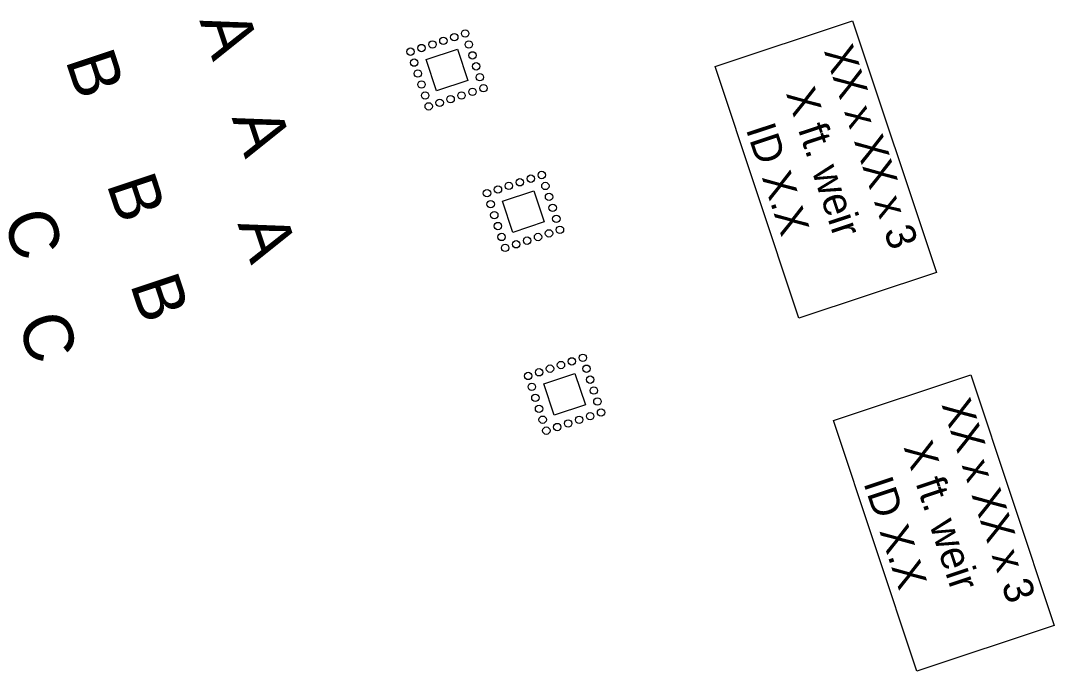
# Model space of a CAD drawing. Extents: x 400935 to 481562, y 415700 to 505362.
# Drawn here: x 402545.2 to 402858.9, y 417970 to 418167.5 of the extents above; entities that cross this region are included whole.
import ezdxf

# ---------------------------------------------------------------- set-up
doc = ezdxf.new("R2010")
doc.units = 0
for name, color, linetype in [('Label A Both CELL', 7, 'Continuous'), ('Label A CG CELL', 7, 'Continuous'), ('Label A Final CELL', 7, 'Continuous'), ('Label B Both CELL', 7, 'Continuous'), ('Label B CG CELL', 7, 'Continuous'), ('Label B Final CELL', 7, 'Continuous'), ('Label C Both CELL', 7, 'Continuous'), ('Label C Final CELL', 7, 'Continuous'), ('Rock Inlet Sediment Trap Type C Both CELL', 7, 'Continuous'), ('Rock Inlet Sediment Trap Type C CG CELL', 7, 'Continuous'), ('Rock Inlet Sediment Trap Type C Final CELL', 7, 'Continuous'), ('Sediment Dam B Note Both CELL', 7, 'Continuous'), ('Sediment Dam B Note Final CELL', 7, 'Continuous')]:
    doc.layers.add(name, color=color, linetype=linetype)

msp = doc.modelspace()

# ---------------------------------------------------------------- linework, layer by layer
at = {"layer": 'Rock Inlet Sediment Trap Type C Both CELL'}
msp.add_lwpolyline([(402700.96, 418115.87), (402704.11, 418106.38), (402694.62, 418103.22), (402691.48, 418112.72)], close=True, dxfattribs=at)
msp.add_lwpolyline([(402700.96, 418115.87), (402704.11, 418106.38), (402694.62, 418103.22), (402691.48, 418112.72)], close=True, dxfattribs=at)
msp.add_lwpolyline([(402700.96, 418115.87), (402704.11, 418106.38), (402694.62, 418103.22), (402691.48, 418112.72)], close=True, dxfattribs=at)
msp.add_lwpolyline([(402700.96, 418115.87), (402704.11, 418106.38), (402694.62, 418103.22), (402691.48, 418112.72)], close=True, dxfattribs=at)
msp.add_lwpolyline([(402700.96, 418115.87), (402704.11, 418106.38), (402694.62, 418103.22), (402691.48, 418112.72)], close=True, dxfattribs=at)
msp.add_lwpolyline([(402700.96, 418115.87), (402704.11, 418106.38), (402694.62, 418103.22), (402691.48, 418112.72)], close=True, dxfattribs=at)
for centre in [(402703.35, 418120.62), (402703.35, 418120.62), (402703.35, 418120.62), (402703.35, 418120.62), (402703.35, 418120.62), (402703.35, 418120.62), (402693.39, 418117.31), (402693.39, 418117.31), (402693.39, 418117.31), (402693.39, 418117.31), (402693.39, 418117.31), (402693.39, 418117.31), (402696.71, 418118.41), (402696.71, 418118.41), (402696.71, 418118.41), (402696.71, 418118.41), (402696.71, 418118.41), (402696.71, 418118.41), (402700.03, 418119.52), (402700.03, 418119.52), (402700.03, 418119.52), (402700.03, 418119.52), (402700.03, 418119.52), (402700.03, 418119.52), (402704.45, 418117.3), (402704.45, 418117.3), (402704.45, 418117.3), (402704.45, 418117.3), (402704.45, 418117.3), (402704.45, 418117.3), (402686.74, 418115.1), (402686.74, 418115.1), (402686.74, 418115.1), (402686.74, 418115.1), (402686.74, 418115.1), (402686.74, 418115.1), (402690.06, 418116.21), (402690.06, 418116.21), (402690.06, 418116.21), (402690.06, 418116.21), (402690.06, 418116.21), (402690.06, 418116.21), (402705.56, 418113.98), (402705.56, 418113.98), (402705.56, 418113.98), (402705.56, 418113.98), (402705.56, 418113.98), (402705.56, 418113.98), (402687.85, 418111.78), (402687.85, 418111.78), (402687.85, 418111.78), (402687.85, 418111.78), (402687.85, 418111.78), (402687.85, 418111.78), (402688.95, 418108.46), (402688.95, 418108.46), (402688.95, 418108.46), (402688.95, 418108.46), (402688.95, 418108.46), (402688.95, 418108.46), (402706.66, 418110.66), (402706.66, 418110.66), (402706.66, 418110.66), (402706.66, 418110.66), (402706.66, 418110.66), (402706.66, 418110.66), (402690.05, 418105.14), (402690.05, 418105.14), (402690.05, 418105.14), (402690.05, 418105.14), (402690.05, 418105.14), (402690.05, 418105.14), (402707.77, 418107.34), (402707.77, 418107.34), (402707.77, 418107.34), (402707.77, 418107.34), (402707.77, 418107.34), (402707.77, 418107.34), (402691.16, 418101.82), (402691.16, 418101.82), (402691.16, 418101.82), (402691.16, 418101.82), (402691.16, 418101.82), (402691.16, 418101.82), (402702.23, 418101.81), (402702.23, 418101.81), (402702.23, 418101.81), (402702.23, 418101.81), (402702.23, 418101.81), (402702.23, 418101.81), (402705.55, 418102.91), (402705.55, 418102.91), (402705.55, 418102.91), (402705.55, 418102.91), (402705.55, 418102.91), (402705.55, 418102.91), (402708.87, 418104.01), (402708.87, 418104.01), (402708.87, 418104.01), (402708.87, 418104.01), (402708.87, 418104.01), (402708.87, 418104.01), (402692.26, 418098.5), (402692.26, 418098.5), (402692.26, 418098.5), (402692.26, 418098.5), (402692.26, 418098.5), (402692.26, 418098.5), (402695.58, 418099.6), (402695.58, 418099.6), (402695.58, 418099.6), (402695.58, 418099.6), (402695.58, 418099.6), (402695.58, 418099.6), (402698.9, 418100.7), (402698.9, 418100.7), (402698.9, 418100.7), (402698.9, 418100.7), (402698.9, 418100.7), (402698.9, 418100.7)]:
    msp.add_circle(centre, 1.12, dxfattribs=at)
at = {"layer": 'Rock Inlet Sediment Trap Type C CG CELL'}
msp.add_lwpolyline([(402677.74, 418158.82), (402680.9, 418149.33), (402671.41, 418146.17), (402668.26, 418155.67)], close=True, dxfattribs=at)
msp.add_lwpolyline([(402677.74, 418158.82), (402680.9, 418149.33), (402671.41, 418146.17), (402668.26, 418155.67)], close=True, dxfattribs=at)
msp.add_lwpolyline([(402677.74, 418158.82), (402680.9, 418149.33), (402671.41, 418146.17), (402668.26, 418155.67)], close=True, dxfattribs=at)
msp.add_lwpolyline([(402677.74, 418158.82), (402680.9, 418149.33), (402671.41, 418146.17), (402668.26, 418155.67)], close=True, dxfattribs=at)
msp.add_lwpolyline([(402677.74, 418158.82), (402680.9, 418149.33), (402671.41, 418146.17), (402668.26, 418155.67)], close=True, dxfattribs=at)
msp.add_lwpolyline([(402677.74, 418158.82), (402680.9, 418149.33), (402671.41, 418146.17), (402668.26, 418155.67)], close=True, dxfattribs=at)
for centre in [(402673.49, 418161.36), (402673.49, 418161.36), (402673.49, 418161.36), (402673.49, 418161.36), (402673.49, 418161.36), (402673.49, 418161.36), (402676.81, 418162.47), (402676.81, 418162.47), (402676.81, 418162.47), (402676.81, 418162.47), (402676.81, 418162.47), (402676.81, 418162.47), (402680.13, 418163.57), (402680.13, 418163.57), (402680.13, 418163.57), (402680.13, 418163.57), (402680.13, 418163.57), (402680.13, 418163.57), (402663.53, 418158.05), (402663.53, 418158.05), (402663.53, 418158.05), (402663.53, 418158.05), (402663.53, 418158.05), (402663.53, 418158.05), (402666.85, 418159.16), (402666.85, 418159.16), (402666.85, 418159.16), (402666.85, 418159.16), (402666.85, 418159.16), (402666.85, 418159.16), (402670.17, 418160.26), (402670.17, 418160.26), (402670.17, 418160.26), (402670.17, 418160.26), (402670.17, 418160.26), (402670.17, 418160.26), (402681.24, 418160.25), (402681.24, 418160.25), (402681.24, 418160.25), (402681.24, 418160.25), (402681.24, 418160.25), (402681.24, 418160.25), (402664.63, 418154.73), (402664.63, 418154.73), (402664.63, 418154.73), (402664.63, 418154.73), (402664.63, 418154.73), (402664.63, 418154.73), (402682.34, 418156.93), (402682.34, 418156.93), (402682.34, 418156.93), (402682.34, 418156.93), (402682.34, 418156.93), (402682.34, 418156.93), (402683.44, 418153.61), (402683.44, 418153.61), (402683.44, 418153.61), (402683.44, 418153.61), (402683.44, 418153.61), (402683.44, 418153.61), (402665.73, 418151.41), (402665.73, 418151.41), (402665.73, 418151.41), (402665.73, 418151.41), (402665.73, 418151.41), (402665.73, 418151.41), (402684.55, 418150.29), (402684.55, 418150.29), (402684.55, 418150.29), (402684.55, 418150.29), (402684.55, 418150.29), (402684.55, 418150.29), (402666.84, 418148.09), (402666.84, 418148.09), (402666.84, 418148.09), (402666.84, 418148.09), (402666.84, 418148.09), (402666.84, 418148.09), (402682.33, 418145.86), (402682.33, 418145.86), (402682.33, 418145.86), (402682.33, 418145.86), (402682.33, 418145.86), (402682.33, 418145.86), (402685.65, 418146.96), (402685.65, 418146.96), (402685.65, 418146.96), (402685.65, 418146.96), (402685.65, 418146.96), (402685.65, 418146.96), (402667.94, 418144.77), (402667.94, 418144.77), (402667.94, 418144.77), (402667.94, 418144.77), (402667.94, 418144.77), (402667.94, 418144.77), (402672.37, 418142.55), (402672.37, 418142.55), (402672.37, 418142.55), (402672.37, 418142.55), (402672.37, 418142.55), (402672.37, 418142.55), (402675.69, 418143.65), (402675.69, 418143.65), (402675.69, 418143.65), (402675.69, 418143.65), (402675.69, 418143.65), (402675.69, 418143.65), (402679.01, 418144.76), (402679.01, 418144.76), (402679.01, 418144.76), (402679.01, 418144.76), (402679.01, 418144.76), (402679.01, 418144.76), (402669.04, 418141.45), (402669.04, 418141.45), (402669.04, 418141.45), (402669.04, 418141.45), (402669.04, 418141.45), (402669.04, 418141.45)]:
    msp.add_circle(centre, 1.12, dxfattribs=at)
at = {"layer": 'Rock Inlet Sediment Trap Type C Final CELL'}
msp.add_lwpolyline([(402713.43, 418060.41), (402716.59, 418050.92), (402707.1, 418047.76), (402703.96, 418057.26)], close=True, dxfattribs=at)
msp.add_lwpolyline([(402713.43, 418060.41), (402716.59, 418050.92), (402707.1, 418047.76), (402703.96, 418057.26)], close=True, dxfattribs=at)
msp.add_lwpolyline([(402713.43, 418060.41), (402716.59, 418050.92), (402707.1, 418047.76), (402703.96, 418057.26)], close=True, dxfattribs=at)
msp.add_lwpolyline([(402713.43, 418060.41), (402716.59, 418050.92), (402707.1, 418047.76), (402703.96, 418057.26)], close=True, dxfattribs=at)
msp.add_lwpolyline([(402713.43, 418060.41), (402716.59, 418050.92), (402707.1, 418047.76), (402703.96, 418057.26)], close=True, dxfattribs=at)
msp.add_lwpolyline([(402713.43, 418060.41), (402716.59, 418050.92), (402707.1, 418047.76), (402703.96, 418057.26)], close=True, dxfattribs=at)
for centre in [(402712.5, 418064.06), (402712.5, 418064.06), (402712.5, 418064.06), (402712.5, 418064.06), (402712.5, 418064.06), (402712.5, 418064.06), (402715.82, 418065.16), (402715.82, 418065.16), (402715.82, 418065.16), (402715.82, 418065.16), (402715.82, 418065.16), (402715.82, 418065.16), (402702.54, 418060.75), (402702.54, 418060.75), (402702.54, 418060.75), (402702.54, 418060.75), (402702.54, 418060.75), (402702.54, 418060.75), (402705.86, 418061.85), (402705.86, 418061.85), (402705.86, 418061.85), (402705.86, 418061.85), (402705.86, 418061.85), (402705.86, 418061.85), (402709.18, 418062.95), (402709.18, 418062.95), (402709.18, 418062.95), (402709.18, 418062.95), (402709.18, 418062.95), (402709.18, 418062.95), (402716.93, 418061.84), (402716.93, 418061.84), (402716.93, 418061.84), (402716.93, 418061.84), (402716.93, 418061.84), (402716.93, 418061.84), (402699.22, 418059.64), (402699.22, 418059.64), (402699.22, 418059.64), (402699.22, 418059.64), (402699.22, 418059.64), (402699.22, 418059.64), (402718.03, 418058.52), (402718.03, 418058.52), (402718.03, 418058.52), (402718.03, 418058.52), (402718.03, 418058.52), (402718.03, 418058.52), (402700.32, 418056.32), (402700.32, 418056.32), (402700.32, 418056.32), (402700.32, 418056.32), (402700.32, 418056.32), (402700.32, 418056.32), (402719.14, 418055.2), (402719.14, 418055.2), (402719.14, 418055.2), (402719.14, 418055.2), (402719.14, 418055.2), (402719.14, 418055.2), (402701.42, 418053), (402701.42, 418053), (402701.42, 418053), (402701.42, 418053), (402701.42, 418053), (402701.42, 418053), (402720.24, 418051.88), (402720.24, 418051.88), (402720.24, 418051.88), (402720.24, 418051.88), (402720.24, 418051.88), (402720.24, 418051.88), (402702.53, 418049.68), (402702.53, 418049.68), (402702.53, 418049.68), (402702.53, 418049.68), (402702.53, 418049.68), (402702.53, 418049.68), (402721.34, 418048.55), (402721.34, 418048.55), (402721.34, 418048.55), (402721.34, 418048.55), (402721.34, 418048.55), (402721.34, 418048.55), (402703.63, 418046.36), (402703.63, 418046.36), (402703.63, 418046.36), (402703.63, 418046.36), (402703.63, 418046.36), (402703.63, 418046.36), (402711.38, 418045.24), (402711.38, 418045.24), (402711.38, 418045.24), (402711.38, 418045.24), (402711.38, 418045.24), (402711.38, 418045.24), (402714.7, 418046.35), (402714.7, 418046.35), (402714.7, 418046.35), (402714.7, 418046.35), (402714.7, 418046.35), (402714.7, 418046.35), (402718.02, 418047.45), (402718.02, 418047.45), (402718.02, 418047.45), (402718.02, 418047.45), (402718.02, 418047.45), (402718.02, 418047.45), (402704.74, 418043.04), (402704.74, 418043.04), (402704.74, 418043.04), (402704.74, 418043.04), (402704.74, 418043.04), (402704.74, 418043.04), (402708.06, 418044.14), (402708.06, 418044.14), (402708.06, 418044.14), (402708.06, 418044.14), (402708.06, 418044.14), (402708.06, 418044.14)]:
    msp.add_circle(centre, 1.12, dxfattribs=at)
at = {"layer": 'Sediment Dam B Note Both CELL'}
msp.add_lwpolyline([(402797.71, 418167.46), (402823.11, 418091.04), (402781.39, 418077.17), (402755.98, 418153.59)], close=True, dxfattribs=at)
msp.add_lwpolyline([(402797.71, 418167.46), (402823.11, 418091.04), (402781.39, 418077.17), (402755.98, 418153.59)], close=True, dxfattribs=at)
msp.add_lwpolyline([(402797.71, 418167.46), (402823.11, 418091.04), (402781.39, 418077.17), (402755.98, 418153.59)], close=True, dxfattribs=at)
msp.add_lwpolyline([(402797.71, 418167.46), (402823.11, 418091.04), (402781.39, 418077.17), (402755.98, 418153.59)], close=True, dxfattribs=at)
msp.add_lwpolyline([(402797.71, 418167.46), (402823.11, 418091.04), (402781.39, 418077.17), (402755.98, 418153.59)], close=True, dxfattribs=at)
msp.add_lwpolyline([(402797.71, 418167.46), (402823.11, 418091.04), (402781.39, 418077.17), (402755.98, 418153.59)], close=True, dxfattribs=at)
at = {"layer": 'Sediment Dam B Note Final CELL'}
msp.add_lwpolyline([(402833.61, 418059.98), (402858.91, 417983.87), (402817.18, 417970), (402791.89, 418046.1)], close=True, dxfattribs=at)
msp.add_lwpolyline([(402833.61, 418059.98), (402858.91, 417983.87), (402817.18, 417970), (402791.89, 418046.1)], close=True, dxfattribs=at)
msp.add_lwpolyline([(402833.61, 418059.98), (402858.91, 417983.87), (402817.18, 417970), (402791.89, 418046.1)], close=True, dxfattribs=at)
msp.add_lwpolyline([(402833.61, 418059.98), (402858.91, 417983.87), (402817.18, 417970), (402791.89, 418046.1)], close=True, dxfattribs=at)
msp.add_lwpolyline([(402833.61, 418059.98), (402858.91, 417983.87), (402817.18, 417970), (402791.89, 418046.1)], close=True, dxfattribs=at)
msp.add_lwpolyline([(402833.61, 418059.98), (402858.91, 417983.87), (402817.18, 417970), (402791.89, 418046.1)], close=True, dxfattribs=at)

# ---------------------------------------------------------------- texts
at = {"layer": 'Label A Both CELL'}
msp.add_text('A', height=15, rotation=288.3867, dxfattribs=at).set_placement((402609.21, 418137.97))
msp.add_text('A', height=15, rotation=288.3867, dxfattribs=at).set_placement((402609.21, 418137.97))
msp.add_text('A', height=15, rotation=288.3867, dxfattribs=at).set_placement((402609.21, 418137.97))
msp.add_text('A', height=15, rotation=288.3867, dxfattribs=at).set_placement((402609.21, 418137.97))
msp.add_text('A', height=15, rotation=288.3867, dxfattribs=at).set_placement((402609.21, 418137.97))
msp.add_text('A', height=15, rotation=288.3867, dxfattribs=at).set_placement((402609.21, 418137.97))
at = {"layer": 'Label A CG CELL'}
msp.add_text('A', height=15, rotation=288.3867, dxfattribs=at).set_placement((402599.4, 418167.5))
msp.add_text('A', height=15, rotation=288.3867, dxfattribs=at).set_placement((402599.4, 418167.5))
msp.add_text('A', height=15, rotation=288.3867, dxfattribs=at).set_placement((402599.4, 418167.5))
msp.add_text('A', height=15, rotation=288.3867, dxfattribs=at).set_placement((402599.4, 418167.5))
msp.add_text('A', height=15, rotation=288.3867, dxfattribs=at).set_placement((402599.4, 418167.5))
msp.add_text('A', height=15, rotation=288.3867, dxfattribs=at).set_placement((402599.4, 418167.5))
at = {"layer": 'Label A Final CELL'}
msp.add_text('A', height=15, rotation=288.3867, dxfattribs=at).set_placement((402610.97, 418105.78))
msp.add_text('A', height=15, rotation=288.3867, dxfattribs=at).set_placement((402610.97, 418105.78))
msp.add_text('A', height=15, rotation=288.3867, dxfattribs=at).set_placement((402610.97, 418105.78))
msp.add_text('A', height=15, rotation=288.3867, dxfattribs=at).set_placement((402610.97, 418105.78))
msp.add_text('A', height=15, rotation=288.3867, dxfattribs=at).set_placement((402610.97, 418105.78))
msp.add_text('A', height=15, rotation=288.3867, dxfattribs=at).set_placement((402610.97, 418105.78))
at = {"layer": 'Label B Both CELL'}
msp.add_text('B', height=15, rotation=288.3867, dxfattribs=at).set_placement((402571.17, 418117.93))
msp.add_text('B', height=15, rotation=288.3867, dxfattribs=at).set_placement((402571.17, 418117.93))
msp.add_text('B', height=15, rotation=288.3867, dxfattribs=at).set_placement((402571.17, 418117.93))
msp.add_text('B', height=15, rotation=288.3867, dxfattribs=at).set_placement((402571.17, 418117.93))
msp.add_text('B', height=15, rotation=288.3867, dxfattribs=at).set_placement((402571.17, 418117.93))
msp.add_text('B', height=15, rotation=288.3867, dxfattribs=at).set_placement((402571.17, 418117.93))
at = {"layer": 'Label B CG CELL'}
msp.add_text('B', height=15, rotation=288.3867, dxfattribs=at).set_placement((402558.68, 418155.5))
msp.add_text('B', height=15, rotation=288.3867, dxfattribs=at).set_placement((402558.68, 418155.5))
msp.add_text('B', height=15, rotation=288.3867, dxfattribs=at).set_placement((402558.68, 418155.5))
msp.add_text('B', height=15, rotation=288.3867, dxfattribs=at).set_placement((402558.68, 418155.5))
msp.add_text('B', height=15, rotation=288.3867, dxfattribs=at).set_placement((402558.68, 418155.5))
msp.add_text('B', height=15, rotation=288.3867, dxfattribs=at).set_placement((402558.68, 418155.5))
at = {"layer": 'Label B Final CELL'}
msp.add_text('B', height=15, rotation=288.3867, dxfattribs=at).set_placement((402578.3, 418087.52))
msp.add_text('B', height=15, rotation=288.3867, dxfattribs=at).set_placement((402578.3, 418087.52))
msp.add_text('B', height=15, rotation=288.3867, dxfattribs=at).set_placement((402578.3, 418087.52))
msp.add_text('B', height=15, rotation=288.3867, dxfattribs=at).set_placement((402578.3, 418087.52))
msp.add_text('B', height=15, rotation=288.3867, dxfattribs=at).set_placement((402578.3, 418087.52))
msp.add_text('B', height=15, rotation=288.3867, dxfattribs=at).set_placement((402578.3, 418087.52))
at = {"layer": 'Label C Both CELL'}
msp.add_text('C', height=15, rotation=288.3867, dxfattribs=at).set_placement((402539.7, 418107.4))
msp.add_text('C', height=15, rotation=288.3867, dxfattribs=at).set_placement((402539.7, 418107.4))
msp.add_text('C', height=15, rotation=288.3867, dxfattribs=at).set_placement((402539.7, 418107.4))
msp.add_text('C', height=15, rotation=288.3867, dxfattribs=at).set_placement((402539.7, 418107.4))
msp.add_text('C', height=15, rotation=288.3867, dxfattribs=at).set_placement((402539.7, 418107.4))
msp.add_text('C', height=15, rotation=288.3867, dxfattribs=at).set_placement((402539.7, 418107.4))
at = {"layer": 'Label C Final CELL'}
msp.add_text('C', height=15, rotation=288.3867, dxfattribs=at).set_placement((402544.14, 418076.09))
msp.add_text('C', height=15, rotation=288.3867, dxfattribs=at).set_placement((402544.14, 418076.09))
msp.add_text('C', height=15, rotation=288.3867, dxfattribs=at).set_placement((402544.14, 418076.09))
msp.add_text('C', height=15, rotation=288.3867, dxfattribs=at).set_placement((402544.14, 418076.09))
msp.add_text('C', height=15, rotation=288.3867, dxfattribs=at).set_placement((402544.14, 418076.09))
msp.add_text('C', height=15, rotation=288.3867, dxfattribs=at).set_placement((402544.14, 418076.09))
at = {"layer": 'Sediment Dam B Note Both CELL'}
for s, p in [('XX x XX x 3', (402788.95, 418158.32)), ('XX x XX x 3', (402788.95, 418158.32)), ('XX x XX x 3', (402788.95, 418158.32)), ('XX x XX x 3', (402788.95, 418158.32)), ('XX x XX x 3', (402788.95, 418158.32)), ('XX x XX x 3', (402788.95, 418158.32)), ('X ft. weir', (402777.43, 418145.42)), ('X ft. weir', (402777.43, 418145.42)), ('X ft. weir', (402777.43, 418145.42)), ('X ft. weir', (402777.43, 418145.42)), ('X ft. weir', (402777.43, 418145.42)), ('X ft. weir', (402777.43, 418145.42)), ('ID X.X', (402765.23, 418134.58)), ('ID X.X', (402765.23, 418134.58)), ('ID X.X', (402765.23, 418134.58)), ('ID X.X', (402765.23, 418134.58)), ('ID X.X', (402765.23, 418134.58)), ('ID X.X', (402765.23, 418134.58))]:
    msp.add_text(s, height=9, rotation=288.3867, dxfattribs=at).set_placement(p)
at = {"layer": 'Sediment Dam B Note Final CELL'}
for s, p in [('XX x XX x 3', (402824.63, 418050.97)), ('XX x XX x 3', (402824.63, 418050.97)), ('XX x XX x 3', (402824.63, 418050.97)), ('XX x XX x 3', (402824.63, 418050.97)), ('XX x XX x 3', (402824.63, 418050.97)), ('XX x XX x 3', (402824.63, 418050.97)), ('X ft. weir', (402813.11, 418038.07)), ('X ft. weir', (402813.11, 418038.07)), ('X ft. weir', (402813.11, 418038.07)), ('X ft. weir', (402813.11, 418038.07)), ('X ft. weir', (402813.11, 418038.07)), ('X ft. weir', (402813.11, 418038.07)), ('ID X.X', (402800.91, 418027.23)), ('ID X.X', (402800.91, 418027.23)), ('ID X.X', (402800.91, 418027.23)), ('ID X.X', (402800.91, 418027.23)), ('ID X.X', (402800.91, 418027.23)), ('ID X.X', (402800.91, 418027.23))]:
    msp.add_text(s, height=9, rotation=288.3867, dxfattribs=at).set_placement(p)

doc.saveas('drawing.dxf')
